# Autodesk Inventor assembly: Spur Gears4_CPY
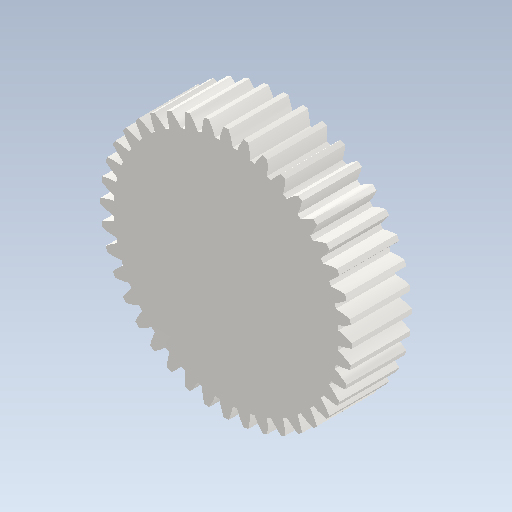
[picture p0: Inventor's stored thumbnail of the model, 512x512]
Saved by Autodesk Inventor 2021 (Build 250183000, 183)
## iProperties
Created: 2021-07
Part Number: Spur Gears4_CPY
Document SubType Name: Assembly
Designer: CHIRAG
Categories: <?xml version="1.0" encoding="UTF-16"?> <MemberInstance><Categories><FamilyTemplate/><ParamToTemplateMap><ParamToTemplate><ParamToTemplate CategoryParameter="//
Author: CHIRAG
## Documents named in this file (2)
- C:\Users\CHIRAG\Documents\Assembly2\Assembly2\trail.2\Design Accelerator\Spur Gears4_CPY.iam
- C:\Users\CHIRAG\Documents\Assembly2\Assembly2\trail.2\Design Accelerator\Spur Gear22_CPY.ipt
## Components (1 placed, 1 different names)
1. Spur Gear2:1
